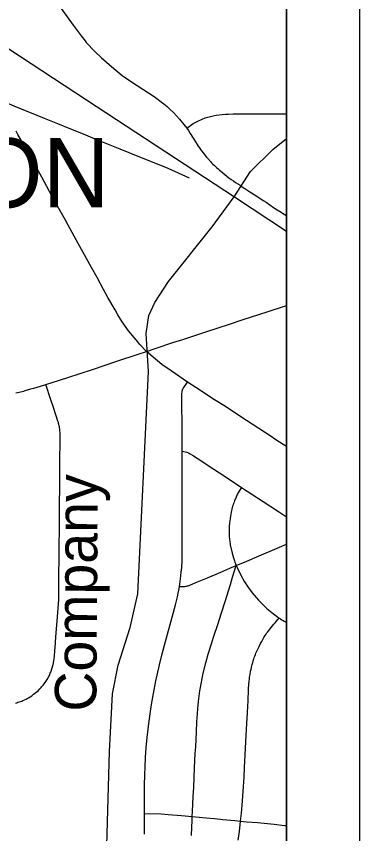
# Model space of a CAD drawing. Extents: x 0 to 34, y 0 to 22.
# Drawn here: x 8.531 to 9, y 17.323 to 18.439 of the extents above; entities that cross this region are included whole.
import ezdxf

# ---------------------------------------------------------------- set-up
doc = ezdxf.new("R2010")
doc.units = 0
for name, color, linetype in [('GM_X_City_Street', 7, 'Continuous'), ('GM_X_Corporation_Text', 7, 'Continuous'), ('GM_X_County_Road', 7, 'Continuous'), ('GM_X_County_Text', 7, 'Continuous'), ('GM_X_Rail_Line', 7, 'Continuous'), ('GM_X_Rail_Line_Text', 7, 'Continuous'), ('GM_X_State_Route', 7, 'Continuous'), ('SH_Cut_Line', 7, 'Continuous'), ('SH_Data', 7, 'Continuous')]:
    doc.layers.add(name, color=color, linetype=linetype)

msp = doc.modelspace()

# ---------------------------------------------------------------- linework, layer by layer
at = {"layer": 'GM_X_City_Street'}
for points in [[(8.4863, 18.3287), (8.4927, 18.3283), (8.4969, 18.3279), (8.5014, 18.3271), (8.5065, 18.3257), (8.5109, 18.324), (8.5157, 18.3221), (8.5276, 18.3172), (8.5378, 18.3129), (8.5592, 18.3044), (8.5692, 18.3003), (8.5874, 18.293), (8.6051, 18.286), (8.6222, 18.2789), (8.6383, 18.2723), (8.6725, 18.2584), (8.6969, 18.2485), (8.7235, 18.2379), (8.738, 18.232), (8.757, 18.2235), (8.7669, 18.219)], [(8.7638, 18.2868), (8.7725, 18.2929), (8.779, 18.2962), (8.785, 18.299), (8.789, 18.3006), (8.7924, 18.3017), (8.7961, 18.3027), (8.7999, 18.3036), (8.8038, 18.3044), (8.8079, 18.305), (8.8122, 18.3055), (8.8166, 18.3058), (8.821, 18.306), (8.8273, 18.3061), (8.8337, 18.3062), (8.8779, 18.3063), (8.9, 18.3063)], [(8.5383, 17.5045), (8.5398, 17.5052), (8.5443, 17.5071), (8.5459, 17.508), (8.5477, 17.5089), (8.5521, 17.5117), (8.5545, 17.5137), (8.5606, 17.5186), (8.563, 17.521), (8.564, 17.522), (8.565, 17.5231), (8.5659, 17.5242), (8.5669, 17.5253), (8.5678, 17.5264), (8.5691, 17.528), (8.5713, 17.5314), (8.573, 17.5339), (8.5753, 17.5379), (8.5761, 17.5396), (8.5766, 17.5409), (8.5773, 17.5424), (8.5779, 17.5439), (8.5785, 17.5455), (8.5797, 17.5487), (8.5813, 17.5544), (8.5818, 17.5567), (8.5824, 17.5599), (8.5826, 17.5615), (8.5828, 17.5631), (8.5829, 17.5647), (8.5837, 17.5741), (8.5839, 17.5773), (8.5851, 17.5923), (8.5868, 17.6135), (8.5882, 17.6313), (8.5886, 17.6373), (8.5889, 17.643), (8.5892, 17.6571), (8.5896, 17.7193), (8.5899, 17.7363), (8.5901, 17.775), (8.5903, 17.7948), (8.5904, 17.8145), (8.5906, 17.8387), (8.5907, 17.8534), (8.5908, 17.8667), (8.5907, 17.8713), (8.5906, 17.8728), (8.5905, 17.8744), (8.5903, 17.8759), (8.5901, 17.8774), (8.5898, 17.879), (8.5895, 17.8805), (8.5892, 17.882), (8.5888, 17.8835), (8.5884, 17.885), (8.5879, 17.8865), (8.5851, 17.8955), (8.5811, 17.9067), (8.5781, 17.916), (8.5713, 17.9365)], [(8.7059, 17.3229), (8.706, 17.3508), (8.7059, 17.3589), (8.706, 17.3892), (8.7064, 17.4044), (8.7068, 17.4141), (8.7074, 17.4276), (8.7084, 17.4405), (8.7097, 17.4547), (8.7115, 17.47), (8.7137, 17.487), (8.7158, 17.4999), (8.7183, 17.515), (8.7217, 17.5322), (8.7234, 17.54), (8.7266, 17.554), (8.7304, 17.5691), (8.7348, 17.5858), (8.7439, 17.6191), (8.7483, 17.6359), (8.7497, 17.6412), (8.751, 17.6467), (8.7522, 17.6518), (8.7534, 17.6576), (8.754, 17.6611), (8.7545, 17.664), (8.7554, 17.6713), (8.7563, 17.6806), (8.7569, 17.6869), (8.7575, 17.6953), (8.7576, 17.7027), (8.7575, 17.8456), (8.7575, 17.8552), (8.7574, 17.8781), (8.7573, 17.9129), (8.7573, 17.9231), (8.7575, 17.9274), (8.7577, 17.9282), (8.7579, 17.9289), (8.7581, 17.9297), (8.7584, 17.9304), (8.7588, 17.9312), (8.7591, 17.9319), (8.7596, 17.9325), (8.7649, 17.9401)], [(8.7575, 17.8456), (8.7598, 17.8454), (8.7618, 17.845), (8.764, 17.8442), (8.7664, 17.8433), (8.7685, 17.8421), (8.7716, 17.8402), (8.7842, 17.8319), (8.7888, 17.8289), (8.8009, 17.821), (8.8162, 17.8111), (8.8388, 17.7962), (8.8464, 17.7911), (8.8681, 17.7769), (8.8889, 17.7632), (8.9, 17.756)], [(8.8388, 17.7962), (8.8369, 17.7935), (8.8353, 17.7909), (8.8345, 17.7897), (8.8338, 17.7884), (8.8331, 17.7871), (8.8324, 17.7858), (8.8318, 17.7844), (8.8312, 17.7831), (8.8291, 17.778), (8.8284, 17.7762), (8.8277, 17.7743), (8.8271, 17.7724), (8.8265, 17.7705), (8.826, 17.7686), (8.8255, 17.7667), (8.825, 17.7648), (8.8236, 17.7575), (8.8229, 17.7533), (8.8224, 17.7479), (8.8219, 17.7429), (8.8219, 17.7398), (8.8219, 17.73), (8.8224, 17.7247), (8.8225, 17.723), (8.8228, 17.7213), (8.823, 17.7197), (8.8233, 17.718), (8.8257, 17.7065), (8.8275, 17.7001), (8.8289, 17.6958), (8.8293, 17.6943), (8.8314, 17.6896), (8.8326, 17.6869), (8.8377, 17.6762), (8.8426, 17.6674), (8.8471, 17.6605), (8.8532, 17.6524), (8.8618, 17.6424), (8.869, 17.6348), (8.8732, 17.6309), (8.8777, 17.6271), (8.8822, 17.6235), (8.89, 17.6179), (8.892, 17.6166), (8.8939, 17.6154), (8.8953, 17.6145), (8.897, 17.6134), (8.9, 17.6116)], [(8.754, 17.6611), (8.7578, 17.6609), (8.7601, 17.661), (8.7613, 17.6611), (8.7624, 17.6613), (8.7635, 17.6615), (8.7647, 17.6617), (8.7658, 17.662), (8.7669, 17.6623), (8.768, 17.6627), (8.769, 17.6631), (8.7787, 17.6671), (8.7921, 17.6729), (8.8103, 17.6806), (8.8225, 17.6858), (8.8314, 17.6896), (8.846, 17.6957), (8.8625, 17.7028), (8.8875, 17.7134), (8.9, 17.7187)], [(8.7702, 17.3209), (8.7707, 17.3329), (8.7711, 17.3406), (8.7714, 17.347), (8.7717, 17.3543), (8.7727, 17.3736), (8.7733, 17.3867), (8.7746, 17.4134), (8.7755, 17.4331), (8.776, 17.442), (8.7771, 17.4626), (8.7777, 17.4763), (8.7783, 17.4869), (8.7788, 17.4943), (8.7798, 17.504), (8.7807, 17.5112), (8.7818, 17.5186), (8.7825, 17.5232), (8.7833, 17.5281), (8.7848, 17.5354), (8.7863, 17.5424), (8.7899, 17.5567), (8.7931, 17.5684), (8.7976, 17.5825), (8.8005, 17.5917), (8.8065, 17.6103), (8.8107, 17.6237), (8.8161, 17.6405), (8.8235, 17.6638), (8.8263, 17.6738), (8.8314, 17.6896)], [(8.8342, 17.3146), (8.8357, 17.3266), (8.8374, 17.3406), (8.8386, 17.3516), (8.8396, 17.3622), (8.8405, 17.3748), (8.8413, 17.3877), (8.8421, 17.4005), (8.8426, 17.414), (8.845, 17.4574), (8.8459, 17.4738), (8.8467, 17.4888), (8.8475, 17.5054), (8.8483, 17.52), (8.8487, 17.5284), (8.8489, 17.5309), (8.8494, 17.5354), (8.8497, 17.5372), (8.8499, 17.5391), (8.8503, 17.5409), (8.8511, 17.5453), (8.8517, 17.5479), (8.8527, 17.5526), (8.8532, 17.5546), (8.8539, 17.5571), (8.8546, 17.5596), (8.8554, 17.5622), (8.8561, 17.5641), (8.8568, 17.566), (8.8575, 17.5679), (8.8583, 17.5698), (8.8591, 17.5717), (8.8625, 17.5788), (8.8647, 17.5833), (8.8662, 17.586), (8.8677, 17.5886), (8.8693, 17.5912), (8.8709, 17.5938), (8.8721, 17.5957), (8.8733, 17.5975), (8.8746, 17.5992), (8.8759, 17.601), (8.879, 17.605), (8.8808, 17.6072), (8.8826, 17.6093), (8.8845, 17.6114), (8.8884, 17.616), (8.89, 17.6179)], [(8.5298, 17.5018), (8.5315, 17.5023), (8.5332, 17.5028), (8.535, 17.5033), (8.5367, 17.5039), (8.5383, 17.5045)], [(8.706, 17.3508), (8.7287, 17.3503), (8.7386, 17.3496), (8.7567, 17.3484), (8.7714, 17.347), (8.7901, 17.3452), (8.8016, 17.3441), (8.8131, 17.343), (8.8295, 17.3414), (8.8374, 17.3406), (8.8453, 17.3398), (8.8604, 17.3385), (8.883, 17.3363), (8.8973, 17.3348), (8.9, 17.3346)]]:
    msp.add_lwpolyline(points, dxfattribs=at)
at = {"layer": 'GM_X_County_Road'}
for points in [[(8.5863, 18.4582), (8.6086, 18.4272), (8.6195, 18.4126), (8.623, 18.4081), (8.6248, 18.4059), (8.6266, 18.4037), (8.6285, 18.4016), (8.6304, 18.3994), (8.6342, 18.3953), (8.6382, 18.3912), (8.6473, 18.3826), (8.6609, 18.3707), (8.6757, 18.3588), (8.6882, 18.3502), (8.7038, 18.3399), (8.7192, 18.3299), (8.7324, 18.32), (8.7369, 18.3161), (8.7412, 18.3121), (8.7455, 18.3079), (8.7497, 18.3035), (8.7539, 18.2988), (8.76, 18.2917), (8.7638, 18.2868), (8.7663, 18.2834), (8.7686, 18.2793), (8.7733, 18.2718), (8.7781, 18.2643), (8.7796, 18.2621), (8.7811, 18.2599), (8.7826, 18.2577), (8.7842, 18.2555), (8.7859, 18.2534), (8.7875, 18.2513), (8.789, 18.2494), (8.7909, 18.2472), (8.7927, 18.2451), (8.7961, 18.2413), (8.7978, 18.2395), (8.7995, 18.2377), (8.8013, 18.236), (8.803, 18.2343), (8.8048, 18.2326), (8.8067, 18.231), (8.8085, 18.2293), (8.8104, 18.2278), (8.8186, 18.2211), (8.8215, 18.2189), (8.8245, 18.2168), (8.8275, 18.2147), (8.8305, 18.2127), (8.8336, 18.2106), (8.8366, 18.2087), (8.8397, 18.2067), (8.8432, 18.2045)], [(8.8432, 18.2045), (8.85, 18.2), (8.858, 18.1947), (8.8615, 18.1924), (8.8649, 18.1901), (8.8684, 18.1878), (8.8722, 18.1855), (8.8773, 18.182), (8.8824, 18.1786), (8.8875, 18.1753), (8.8927, 18.172), (8.8948, 18.1706), (8.8969, 18.1692), (8.899, 18.1679), (8.9, 18.1673)], [(8.7086, 17.982), (8.7218, 17.9862), (8.745, 17.9939), (8.7586, 17.9981), (8.7887, 18.008), (8.8069, 18.014), (8.8207, 18.0186), (8.841, 18.0253), (8.8735, 18.036), (8.9, 18.0447)], [(8.5508, 17.9306), (8.5547, 17.9318), (8.5594, 17.9331), (8.5641, 17.9344), (8.5713, 17.9365), (8.58, 17.9394), (8.6012, 17.9463), (8.6349, 17.9574), (8.6684, 17.9685), (8.6975, 17.9781), (8.7086, 17.982)], [(8.5304, 17.9255), (8.5326, 17.9258), (8.5347, 17.9263), (8.5368, 17.9267), (8.539, 17.9272), (8.5411, 17.9278), (8.5432, 17.9284), (8.5508, 17.9306)]]:
    msp.add_lwpolyline(points, dxfattribs=at)
at = {"layer": 'GM_X_County_Text'}
msp.add_lwpolyline([(6.6171, 15.3291), (8.9, 15.3047), (8.9, 20.9), (2.1, 20.9)], dxfattribs=at)
at = {"layer": 'GM_X_Rail_Line'}
for points in [[(8.9, 18.1458), (8.8289, 18.1924), (8.6267, 18.3248), (8.2615, 18.5646), (8.0005, 18.7359), (7.6576, 18.9613), (7.6455, 18.9696), (7.6343, 18.9779)], [(8.8287, 18.1929), (8.8511, 18.2275), (8.8812, 18.2576), (8.9, 18.2726)], [(8.6506, 17.163), (8.6581, 17.4355), (8.6625, 17.5144), (8.6701, 17.5536), (8.6865, 17.6048), (8.6968, 17.6508), (8.7114, 17.9545), (8.7083, 18.0062), (8.712, 18.0311), (8.7201, 18.0486), (8.7388, 18.0773), (8.7987, 18.1521), (8.8287, 18.1929)]]:
    msp.add_lwpolyline(points, dxfattribs=at)
at = {"layer": 'GM_X_State_Route'}
msp.add_lwpolyline([(8.9, 17.8519), (8.8953, 17.855), (8.8857, 17.8613), (8.8779, 17.8665), (8.8701, 17.8716), (8.8623, 17.8767), (8.8365, 17.8936), (8.8166, 17.9065), (8.8018, 17.9159), (8.7761, 17.9328), (8.7649, 17.9401), (8.7427, 17.9552), (8.7297, 17.9642), (8.7178, 17.974), (8.7086, 17.982), (8.6997, 17.9915), (8.6946, 17.9977), (8.6842, 18.0102), (8.6757, 18.0224), (8.6698, 18.032), (8.6661, 18.0386), (8.6562, 18.0557), (8.6502, 18.0666), (8.6412, 18.0829), (8.6336, 18.0966), (8.6154, 18.1294), (8.6018, 18.1541), (8.598, 18.1611), (8.591, 18.1737), (8.585, 18.1843), (8.5764, 18.2001), (8.5656, 18.2198), (8.5594, 18.2312), (8.5552, 18.2386), (8.5511, 18.2459), (8.5469, 18.2533), (8.5404, 18.2652), (8.538, 18.2695), (8.5331, 18.2782), (8.5306, 18.2825)], dxfattribs=at)
at = {"layer": 'SH_Cut_Line'}
msp.add_lwpolyline([(6.6171, 15.3291), (8.9, 15.3047), (8.9, 20.9), (2.1, 20.9)], dxfattribs=at)
at = {"layer": 'SH_Data'}
for p, q in [((9, 21), (9, 14)), ((8.9, 20.9), (8.9, 14.1))]:
    msp.add_line(p, q, dxfattribs=at)

# ---------------------------------------------------------------- texts
at = {"layer": 'GM_X_Corporation_Text'}
msp.add_text('SOLON', height=0.0947, rotation=0, dxfattribs=at).set_placement((8.2151, 18.1784))
at = {"layer": 'GM_X_Rail_Line_Text'}
msp.add_text('Company', height=0.05663, rotation=89.6023, dxfattribs=at).set_placement((8.6401, 17.4899))

doc.saveas('drawing.dxf')
